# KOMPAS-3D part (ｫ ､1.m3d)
File: created 04.01.2016 18:05:13, last saved 27.07.2016 13:38:09.
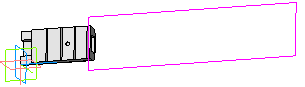
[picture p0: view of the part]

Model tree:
1. Эскиз:1
2. Операция выдавливания:1
     Расстояние 1 = 20
3. Эскиз:2
4. Операция выдавливания:2
     Расстояние 1 = 400
5. Эскиз:3
6. Вырезать элемент выдавливания:1
     Расстояние 1 = 70
7. Эскиз:4
8. Вырезать элемент выдавливания:2
     Расстояние 1 = 2
9. Эскиз:5
10. Эскиз:6
11. Вырезать элемент выдавливания:3
     Расстояние 2 = 40; Расстояние 1 = 36
12. Эскиз:7
13. Вырезать элемент выдавливания:4
     Расстояние 1 = 50
14. Эскиз:8
15. Эскиз:9
16. Вырезать элемент выдавливания:5
     Расстояние 1 = 30
17. Эскиз:10
18. Вырезать элемент выдавливания:6
     Расстояние 1 = 30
